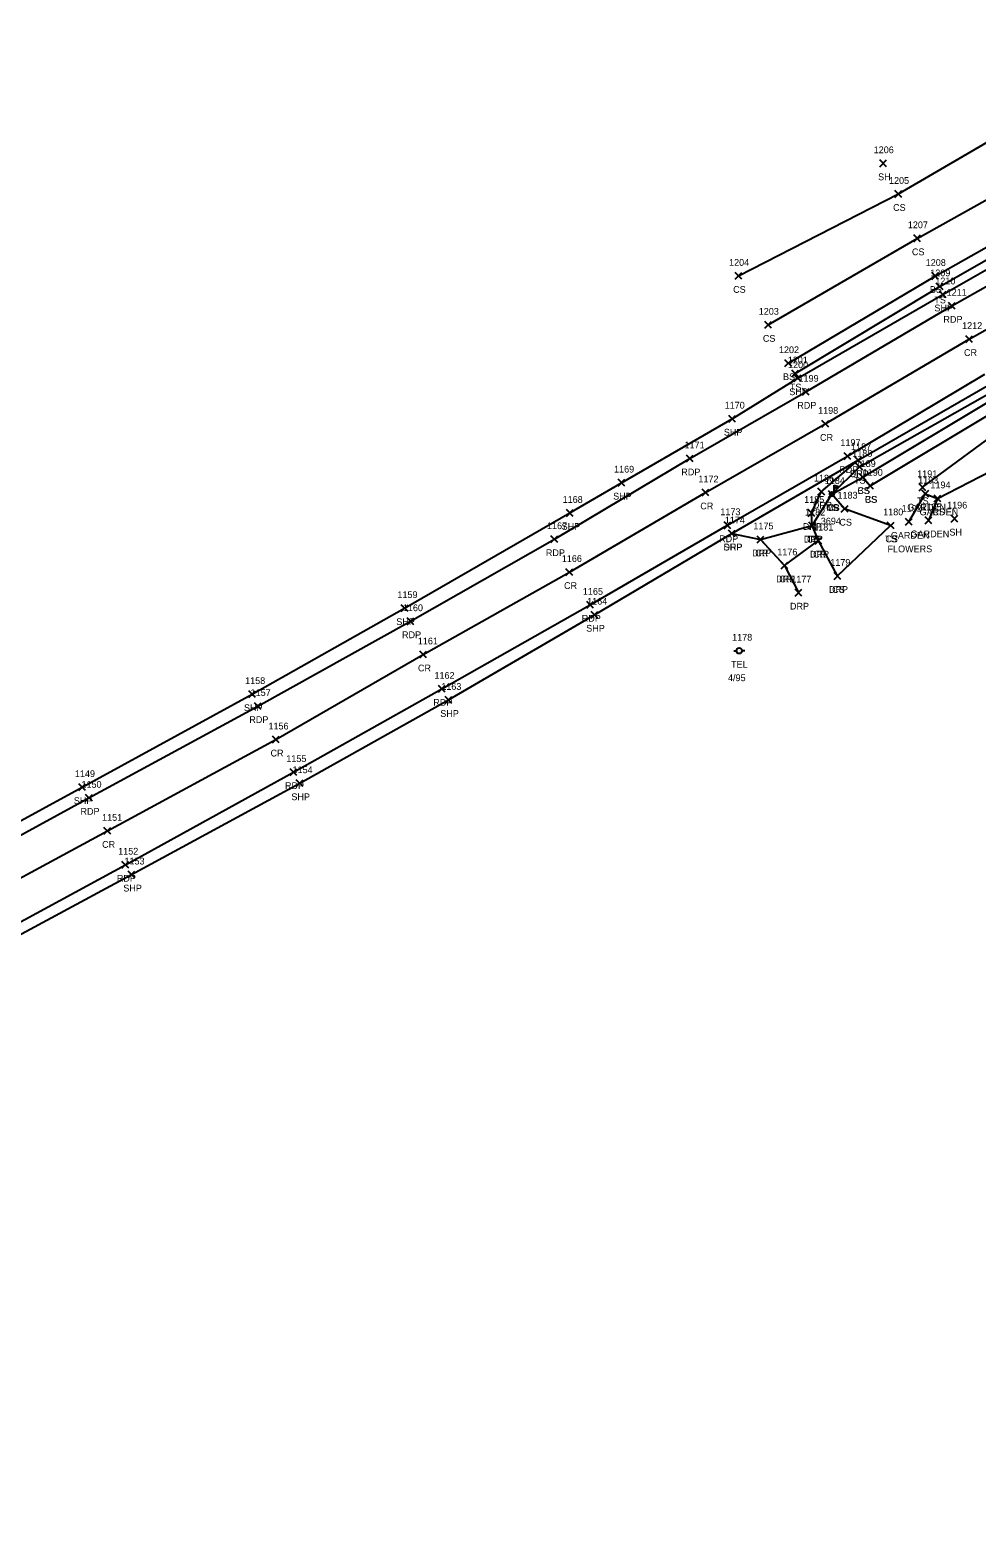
# Model space of a CAD drawing. Extents: x 1606530 to 1613020, y 784959 to 789666.
# Drawn here: x 1608585 to 1608865.5, y 787945.8 to 788392.4 of the extents above; entities that cross this region are included whole.
import ezdxf

# ---------------------------------------------------------------- set-up
doc = ezdxf.new("R2010")
doc.units = 0
for name, color, linetype in [('L_A', 7, 'Continuous'), ('L_C', 7, 'Continuous'), ('L_I', 7, 'Continuous'), ('L_TIC', 7, 'Continuous'), ('LAPB', 7, 'Continuous'), ('LELB', 7, 'Continuous'), ('LMB', 7, 'Continuous'), ('P_A', 7, 'Continuous'), ('P_I', 7, 'Continuous'), ('P_TIC', 7, 'Continuous'), ('PET', 7, 'Continuous'), ('PRC', 7, 'Continuous'), ('PSP', 7, 'Continuous'), ('R_A', 7, 'Continuous'), ('R_I', 7, 'Continuous'), ('R_TIC', 7, 'Continuous'), ('RDP', 7, 'Continuous'), ('U_A', 7, 'Continuous'), ('U_C', 7, 'Continuous'), ('U_I', 7, 'Continuous'), ('UP', 7, 'Continuous')]:
    doc.layers.add(name, color=color, linetype=linetype)

msp = doc.modelspace()

# ---------------------------------------------------------------- linework, layer by layer
at = {"layer": 'L_TIC'}
for points in [[(1608836.75, 788351.95), (1608838.75, 788353.95)], [(1608838.75, 788351.95), (1608836.75, 788353.95)], [(1608841.24, 788342.87), (1608843.24, 788344.87)], [(1608843.24, 788342.87), (1608841.24, 788344.87)], [(1608846.82, 788329.73), (1608848.82, 788331.73)], [(1608848.82, 788329.73), (1608846.82, 788331.73)], [(1608793.85, 788318.6), (1608795.85, 788320.6)], [(1608795.85, 788318.6), (1608793.85, 788320.6)], [(1608852.13, 788318.57), (1608854.13, 788320.57)], [(1608854.13, 788318.57), (1608852.13, 788320.57)], [(1608853.48, 788315.49), (1608855.48, 788317.49)], [(1608855.48, 788315.49), (1608853.48, 788317.49)], [(1608802.65, 788304.1), (1608804.65, 788306.1)], [(1608804.65, 788304.1), (1608802.65, 788306.1)], [(1608808.64, 788292.73), (1608810.64, 788294.73)], [(1608810.64, 788292.73), (1608808.64, 788294.73)], [(1608810.68, 788289.67), (1608812.68, 788291.67)], [(1608812.68, 788289.67), (1608810.68, 788291.67)], [(1608829.7, 788262.06), (1608831.7, 788264.06)], [(1608831.7, 788262.06), (1608829.7, 788264.06)], [(1608830.71, 788259.02), (1608832.71, 788261.02)], [(1608832.71, 788259.02), (1608830.71, 788261.02)], [(1608830.71, 788259.02), (1608832.71, 788261.02)], [(1608832.71, 788259.02), (1608830.71, 788261.02)], [(1608821.56, 788253.99), (1608823.56, 788255.99)], [(1608823.56, 788253.99), (1608821.56, 788255.99)], [(1608821.56, 788253.99), (1608823.56, 788255.99)], [(1608823.56, 788253.99), (1608821.56, 788255.99)], [(1608832.88, 788256.4), (1608834.88, 788258.4)], [(1608834.88, 788256.4), (1608832.88, 788258.4)], [(1608832.88, 788256.4), (1608834.88, 788258.4)], [(1608834.88, 788256.4), (1608832.88, 788258.4)], [(1608848.38, 788255.99), (1608850.38, 788257.99)], [(1608850.38, 788255.99), (1608848.38, 788257.99)], [(1608849.23, 788254.11), (1608851.23, 788256.11)], [(1608851.23, 788254.11), (1608849.23, 788256.11)], [(1608825.32, 788249.65), (1608827.32, 788251.65)], [(1608827.32, 788249.65), (1608825.32, 788251.65)], [(1608852.86, 788252.71), (1608854.86, 788254.71)], [(1608854.86, 788252.71), (1608852.86, 788254.71)], [(1608852.86, 788252.71), (1608854.86, 788254.71)], [(1608854.86, 788252.71), (1608852.86, 788254.71)], [(1608844.34, 788245.75), (1608846.34, 788247.75)], [(1608846.34, 788245.75), (1608844.34, 788247.75)], [(1608850.2, 788246.2), (1608852.2, 788248.2)], [(1608852.2, 788246.2), (1608850.2, 788248.2)], [(1608857.87, 788246.71), (1608859.87, 788248.71)], [(1608859.87, 788246.71), (1608857.87, 788248.71)], [(1608815.75, 788244.64), (1608817.75, 788246.64)], [(1608817.75, 788244.64), (1608815.75, 788246.64)], [(1608838.95, 788244.71), (1608840.95, 788246.71)], [(1608840.95, 788244.71), (1608838.95, 788246.71)], [(1608838.95, 788244.71), (1608840.95, 788246.71)], [(1608840.95, 788244.71), (1608838.95, 788246.71)], [(1608823.19, 788229.73), (1608825.19, 788231.73)], [(1608825.19, 788229.73), (1608823.19, 788231.73)]]:
    msp.add_lwpolyline(points, dxfattribs=at)
at = {"layer": 'LAPB'}
msp.add_lwpolyline([(1608845.34, 788246.75), (1608850.23, 788255.11), (1608853.86, 788253.71), (1608851.2, 788247.2)], dxfattribs=at)
at = {"layer": 'LELB'}
for points in [[(1608831.71, 788260.02), (1608870.92, 788283.54), (1608902.9, 788300.53), (1608905.17, 788302.06), (1608913.86, 788309.86), (1608916.94, 788311.14), (1608945.63, 788325.49), (1608982.98, 788345.36), (1609026.68, 788366.49), (1609062.42, 788381.05), (1609095.63, 788388.11), (1609108.11, 788392.39), (1609116.71, 788392.11), (1609124.65, 788392.27)], [(1608794.85, 788319.6), (1608842.24, 788343.87), (1608885.36, 788369.04), (1608910.12, 788379.88), (1608924.91, 788387.04)], [(1608803.65, 788305.1), (1608847.82, 788330.73), (1608888.11, 788353.15), (1608914.92, 788368.87), (1608930.01, 788374.18)], [(1608853.86, 788253.71), (1608879.11, 788266.69), (1608889.07, 788272.67), (1608908.34, 788283.28), (1608917.54, 788288.2), (1608929.97, 788294.46), (1608949.67, 788303.5), (1608962.88, 788306.16), (1608991.96, 788321.51), (1609035.12, 788349.67), (1609066.9, 788360.54), (1609090.16, 788369.42)], [(1608809.64, 788293.73), (1608853.13, 788319.57), (1608892.85, 788341.93), (1608925.8, 788363.52)], [(1608811.68, 788290.67), (1608854.48, 788316.49), (1608894.21, 788339.18), (1608933.71, 788362.09)], [(1608833.88, 788257.4), (1608872.6, 788280.62), (1608904.01, 788298), (1608902.9, 788300.53)], [(1608849.38, 788256.99), (1608875.12, 788276), (1608906.35, 788297.69), (1608905.17, 788302.06), (1608903.61, 788303.66)], [(1608816.75, 788245.64), (1608822.56, 788254.99), (1608830.7, 788263.06), (1608870.16, 788285.39)], [(1608824.19, 788230.73), (1608839.95, 788245.71), (1608826.32, 788250.65), (1608822.56, 788254.99), (1608831.71, 788260.02), (1608833.88, 788257.4)]]:
    msp.add_lwpolyline(points, dxfattribs=at)
at = {"layer": 'LMB'}
for p, q in [((1608823.21, 788257.59), (1608824.51, 788257.21)), ((1608823.22, 788255), (1608823.22, 788257.6)), ((1608823.22, 788256.69), (1608824.5, 788257.2)), ((1608822.56, 788254.99), (1608822.56, 788254.99))]:
    msp.add_line(p, q, dxfattribs=at)
msp.add_circle((1608822.56, 788254.99), 0.656, dxfattribs=at)
at = {"layer": 'P_TIC'}
for points in [[(1608854.39, 788313.11), (1608856.39, 788315.11)], [(1608856.39, 788313.11), (1608854.39, 788315.11)], [(1608857.1, 788309.73), (1608859.1, 788311.73)], [(1608859.1, 788309.73), (1608857.1, 788311.73)], [(1608862.25, 788299.9), (1608864.25, 788301.9)], [(1608864.25, 788299.9), (1608862.25, 788301.9)], [(1608811.41, 788288.29), (1608813.41, 788290.29)], [(1608813.41, 788288.29), (1608811.41, 788290.29)], [(1608813.8, 788284.27), (1608815.8, 788286.27)], [(1608815.8, 788284.27), (1608813.8, 788286.27)], [(1608791.98, 788276.31), (1608793.98, 788278.31)], [(1608793.98, 788276.31), (1608791.98, 788278.31)], [(1608819.6, 788274.76), (1608821.6, 788276.76)], [(1608821.6, 788274.76), (1608819.6, 788276.76)], [(1608779.44, 788264.54), (1608781.44, 788266.54)], [(1608781.44, 788264.54), (1608779.44, 788266.54)], [(1608826.2, 788265.24), (1608828.2, 788267.24)], [(1608828.2, 788265.24), (1608826.2, 788267.24)], [(1608829.36, 788264), (1608831.36, 788266)], [(1608831.36, 788264), (1608829.36, 788266)], [(1608759.2, 788257.36), (1608761.2, 788259.36)], [(1608761.2, 788257.36), (1608759.2, 788259.36)], [(1608784.13, 788254.45), (1608786.13, 788256.45)], [(1608786.13, 788254.45), (1608784.13, 788256.45)], [(1608743.94, 788248.39), (1608745.94, 788250.39)], [(1608745.94, 788248.39), (1608743.94, 788250.39)], [(1608739.32, 788240.6), (1608741.32, 788242.6)], [(1608741.32, 788240.6), (1608739.32, 788242.6)], [(1608790.64, 788244.74), (1608792.64, 788246.74)], [(1608792.64, 788244.74), (1608790.64, 788246.74)], [(1608791.93, 788242.28), (1608793.93, 788244.28)], [(1608793.93, 788242.28), (1608791.93, 788244.28)], [(1608800.42, 788240.54), (1608802.42, 788242.54)], [(1608802.42, 788240.54), (1608800.42, 788242.54)], [(1608815.75, 788244.64), (1608817.75, 788246.64)], [(1608817.75, 788244.64), (1608815.75, 788246.64)], [(1608817.57, 788240.19), (1608819.57, 788242.19)], [(1608819.57, 788240.19), (1608817.57, 788242.19)], [(1608807.54, 788232.85), (1608809.54, 788234.85)], [(1608809.54, 788232.85), (1608807.54, 788234.85)], [(1608743.76, 788230.88), (1608745.76, 788232.88)], [(1608745.76, 788230.88), (1608743.76, 788232.88)], [(1608694.96, 788220.19), (1608696.96, 788222.19)], [(1608696.96, 788220.19), (1608694.96, 788222.19)], [(1608749.94, 788221.17), (1608751.94, 788223.17)], [(1608751.94, 788221.17), (1608749.94, 788223.17)], [(1608751.22, 788218.24), (1608753.22, 788220.24)], [(1608753.22, 788218.24), (1608751.22, 788220.24)], [(1608696.7, 788216.31), (1608698.7, 788218.31)], [(1608698.7, 788216.31), (1608696.7, 788218.31)], [(1608700.47, 788206.47), (1608702.47, 788208.47)], [(1608702.47, 788206.47), (1608700.47, 788208.47)], [(1608705.97, 788196.28), (1608707.97, 788198.28)], [(1608707.97, 788196.28), (1608705.97, 788198.28)], [(1608649.82, 788194.72), (1608651.82, 788196.72)], [(1608651.82, 788194.72), (1608649.82, 788196.72)], [(1608651.45, 788191.19), (1608653.45, 788193.19)], [(1608653.45, 788191.19), (1608651.45, 788193.19)], [(1608707.99, 788193), (1608709.99, 788195)], [(1608709.99, 788193), (1608707.99, 788195)], [(1608656.8, 788181.27), (1608658.8, 788183.27)], [(1608658.8, 788181.27), (1608656.8, 788183.27)], [(1608662.01, 788171.64), (1608664.01, 788173.64)], [(1608664.01, 788171.64), (1608662.01, 788173.64)], [(1608599.4, 788167.18), (1608601.4, 788169.18)], [(1608601.4, 788167.18), (1608599.4, 788169.18)], [(1608663.87, 788168.33), (1608665.87, 788170.33)], [(1608665.87, 788168.33), (1608663.87, 788170.33)], [(1608601.43, 788164), (1608603.43, 788166)], [(1608603.43, 788164), (1608601.43, 788166)], [(1608606.88, 788154.22), (1608608.88, 788156.22)], [(1608608.88, 788154.22), (1608606.88, 788156.22)], [(1608612.21, 788144.21), (1608614.21, 788146.21)], [(1608614.21, 788144.21), (1608612.21, 788146.21)], [(1608614.07, 788141.28), (1608616.07, 788143.28)], [(1608616.07, 788141.28), (1608614.07, 788143.28)]]:
    msp.add_lwpolyline(points, dxfattribs=at)
at = {"layer": 'PET'}
for points in [[(1608213.49, 787970.47), (1608262.25, 787993.4), (1608276.88, 787999.74), (1608323.57, 788022.14), (1608370.66, 788045.01), (1608417.98, 788068.46), (1608464.64, 788091.66), (1608509.37, 788115.25), (1608554.28, 788138.75), (1608602.43, 788165), (1608652.45, 788192.19), (1608697.7, 788217.31), (1608740.32, 788241.6), (1608780.44, 788265.54), (1608814.8, 788285.27), (1608858.1, 788310.73), (1608896.56, 788332.46)], [(1608222.94, 787950.09), (1608271.33, 787972.62), (1608285.55, 787979.14), (1608332.21, 788001.49), (1608379.48, 788024.01), (1608428.02, 788048.6), (1608475.06, 788071.87), (1608519, 788095), (1608563.86, 788118.44), (1608613.21, 788145.21), (1608663.01, 788172.64), (1608706.97, 788197.28), (1608750.94, 788222.17), (1608791.64, 788245.74), (1608827.2, 788266.24), (1608867.86, 788290.54)]]:
    msp.add_lwpolyline(points, dxfattribs=at)
at = {"layer": 'PRC'}
for points in [[(1608218.84, 787960.71), (1608267.22, 787983.04), (1608281.29, 787989.52), (1608328.06, 788011.76), (1608375.14, 788034.19), (1608423.06, 788058.55), (1608469.95, 788081.45), (1608514.06, 788104.91), (1608558.92, 788128.79), (1608607.88, 788155.22), (1608657.8, 788182.27), (1608701.47, 788207.47), (1608744.76, 788231.88), (1608785.13, 788255.45), (1608820.6, 788275.76), (1608863.25, 788300.9), (1608901.81, 788322.6)], [(1608801.42, 788241.54), (1608816.75, 788245.64)], [(1608808.54, 788233.85), (1608818.57, 788241.19)]]:
    msp.add_lwpolyline(points, dxfattribs=at)
at = {"layer": 'PSP'}
for points in [[(1608211.38, 787974.27), (1608260.55, 787996.78), (1608275.47, 788003.59), (1608321.31, 788025.42), (1608369.02, 788048.35), (1608416.07, 788071.69), (1608462.93, 788095.28), (1608507.55, 788118.54), (1608552.21, 788141.92), (1608600.4, 788168.18), (1608650.82, 788195.72), (1608695.96, 788221.19), (1608744.94, 788249.39), (1608760.2, 788258.36), (1608792.98, 788277.31), (1608812.41, 788289.29), (1608855.39, 788314.11), (1608894.81, 788336.59)], [(1608222.38, 787945.84), (1608249.08, 787958.77), (1608292.52, 787977.73), (1608320.86, 787991.5), (1608334.01, 787997.98), (1608381.01, 788020.88), (1608430, 788045.59), (1608476.4, 788068.65), (1608521.08, 788091.65), (1608567.38, 788116.6), (1608615.07, 788142.28), (1608664.87, 788169.33), (1608708.99, 788194), (1608752.22, 788219.24), (1608792.93, 788243.28), (1608830.36, 788265), (1608869.22, 788287.4)]]:
    msp.add_lwpolyline(points, dxfattribs=at)
at = {"layer": 'R_TIC'}
for points in [[(1608829.36, 788264), (1608831.36, 788266)], [(1608831.36, 788264), (1608829.36, 788266)], [(1608818.41, 788254.7), (1608820.41, 788256.7)], [(1608820.41, 788254.7), (1608818.41, 788256.7)], [(1608815.47, 788248.38), (1608817.47, 788250.38)], [(1608817.47, 788248.38), (1608815.47, 788250.38)], [(1608791.93, 788242.28), (1608793.93, 788244.28)], [(1608793.93, 788242.28), (1608791.93, 788244.28)], [(1608800.42, 788240.54), (1608802.42, 788242.54)], [(1608802.42, 788240.54), (1608800.42, 788242.54)], [(1608815.75, 788244.64), (1608817.75, 788246.64)], [(1608817.75, 788244.64), (1608815.75, 788246.64)], [(1608817.57, 788240.19), (1608819.57, 788242.19)], [(1608819.57, 788240.19), (1608817.57, 788242.19)], [(1608807.54, 788232.85), (1608809.54, 788234.85)], [(1608809.54, 788232.85), (1608807.54, 788234.85)], [(1608823.19, 788229.73), (1608825.19, 788231.73)], [(1608825.19, 788229.73), (1608823.19, 788231.73)], [(1608811.63, 788224.79), (1608813.63, 788226.79)], [(1608813.63, 788224.79), (1608811.63, 788226.79)]]:
    msp.add_lwpolyline(points, dxfattribs=at)
at = {"layer": 'RDP'}
for points in [[(1608824.19, 788230.73), (1608818.57, 788241.19), (1608816.75, 788245.64), (1608816.47, 788249.38), (1608819.41, 788255.7), (1608830.36, 788265)], [(1608792.93, 788243.28), (1608801.42, 788241.54), (1608808.54, 788233.85), (1608812.63, 788225.79)]]:
    msp.add_lwpolyline(points, dxfattribs=at)
at = {"layer": 'UP'}
for p, q in [((1608793.45, 788208.57), (1608794.28, 788208.57)), ((1608795.11, 788208.58), (1608795.11, 788208.58)), ((1608796.78, 788208.58), (1608795.95, 788208.58)), ((1608795.95, 788208.58), (1608795.95, 788208.58)), ((1608796.78, 788208.58), (1608796.78, 788208.58))]:
    msp.add_line(p, q, dxfattribs=at)
msp.add_circle((1608795.11, 788208.58), 0.833, dxfattribs=at)

# ---------------------------------------------------------------- texts
at = {"layer": 'L_A'}
for s, p in [('SH', (1608836.24, 788347.95)), ('CS', (1608840.68, 788338.87)), ('CS', (1608846.26, 788325.73)), ('CS', (1608793.29, 788314.6)), ('BS', (1608851.57, 788314.57)), ('TS', (1608852.89, 788311.49)), ('CS', (1608802.09, 788300.1)), ('BS', (1608808.08, 788288.73)), ('TS', (1608810.09, 788285.67)), ('TS', (1608829.11, 788258.06)), ('CS', (1608830.15, 788255.02)), ('BS', (1608830.15, 788255.02)), ('TS', (1608820.97, 788249.99)), ('MB', (1608820.87, 788249.99)), ('CS', (1608821, 788249.99)), ('CS', (1608832.32, 788252.4)), ('BS', (1608832.32, 788252.4)), ('GARDEN', (1608844.9, 788250.11)), ('TS', (1608847.79, 788251.99)), ('CS', (1608824.77, 788245.65)), ('GARDEN', (1608848.53, 788248.71)), ('CS', (1608852.3, 788248.71)), ('TS', (1608815.16, 788240.64)), ('TS', (1608838.36, 788240.71)), ('CS', (1608838.39, 788240.71)), ('GARDEN', (1608840.01, 788241.75)), ('GARDEN', (1608845.87, 788242.2)), ('SH', (1608857.36, 788242.71)), ('CS', (1608822.63, 788225.73))]:
    msp.add_text(s, height=2, dxfattribs=at).set_placement(p)
at = {"layer": 'L_C'}
for s, p in [('3694', (1608819.26, 788245.99)), ('FLOWERS', (1608839.04, 788237.75))]:
    msp.add_text(s, height=2, dxfattribs=at).set_placement(p)
at = {"layer": 'L_I'}
for s, p in [('1206', (1608834.93, 788355.95)), ('1205', (1608839.47, 788346.87)), ('1207', (1608845.05, 788333.73)), ('1204', (1608792.08, 788322.6)), ('1208', (1608850.35, 788322.57)), ('1209', (1608851.7, 788319.49)), ('1203', (1608800.88, 788308.1)), ('1202', (1608806.86, 788296.73)), ('1201', (1608809.48, 788293.67)), ('1188', (1608828.57, 788266.06)), ('1189', (1608829.58, 788263.02)), ('1189', (1608829.58, 788263.02)), ('1190', (1608831.67, 788260.4)), ('1190', (1608831.67, 788260.4)), ('1191', (1608847.82, 788259.99)), ('1184', (1608820.44, 788257.99)), ('1184', (1608820.44, 788257.99)), ('1184', (1608820.44, 788257.99)), ('1193', (1608848.1, 788258.11)), ('1194', (1608851.74, 788256.71)), ('1194', (1608851.74, 788256.71)), ('1183', (1608824.2, 788253.65)), ('1192', (1608843.22, 788249.75)), ('1195', (1608849.07, 788250.2)), ('1196', (1608856.69, 788250.71)), ('1182', (1608814.62, 788248.64)), ('1180', (1608837.74, 788248.71)), ('1180', (1608837.74, 788248.71)), ('1179', (1608822.06, 788233.73))]:
    msp.add_text(s, height=2, dxfattribs=at).set_placement(p)
at = {"layer": 'P_A'}
for s, p in [('SHP', (1608852.92, 788309.11)), ('RDP', (1608855.59, 788305.73)), ('CR', (1608861.69, 788295.9)), ('SHP', (1608809.94, 788284.29)), ('RDP', (1608812.29, 788280.27)), ('SHP', (1608790.52, 788272.31)), ('CR', (1608819.03, 788270.76)), ('RDP', (1608777.93, 788260.54)), ('RDP', (1608824.69, 788261.24)), ('SHP', (1608827.89, 788260)), ('SHP', (1608757.73, 788253.36)), ('CR', (1608783.56, 788250.45)), ('SHP', (1608742.47, 788244.39)), ('RDP', (1608789.13, 788240.74)), ('CR', (1608815.18, 788240.64)), ('RDP', (1608737.81, 788236.6)), ('SHP', (1608790.47, 788238.28)), ('CR', (1608799.85, 788236.54)), ('CR', (1608817, 788236.19)), ('CR', (1608806.97, 788228.85)), ('CR', (1608743.19, 788226.88)), ('SHP', (1608693.49, 788216.19)), ('RDP', (1608748.43, 788217.17)), ('SHP', (1608749.76, 788214.24)), ('RDP', (1608695.19, 788212.31)), ('CR', (1608699.91, 788202.47)), ('RDP', (1608704.46, 788192.28)), ('SHP', (1608648.36, 788190.72)), ('RDP', (1608649.94, 788187.19)), ('SHP', (1608706.52, 788189)), ('CR', (1608656.23, 788177.27)), ('RDP', (1608660.5, 788167.64)), ('SHP', (1608597.94, 788163.18)), ('RDP', (1608599.92, 788160)), ('SHP', (1608662.41, 788164.33)), ('CR', (1608606.32, 788150.22)), ('RDP', (1608610.7, 788140.21)), ('SHP', (1608612.61, 788137.28))]:
    msp.add_text(s, height=2, dxfattribs=at).set_placement(p)
at = {"layer": 'P_I'}
for s, p in [('1210', (1608853.18, 788317.11)), ('1211', (1608856.54, 788313.73)), ('1212', (1608861.13, 788303.9)), ('1200', (1608809.55, 788292.29)), ('1199', (1608812.66, 788288.27)), ('1170', (1608790.77, 788280.31)), ('1198', (1608818.47, 788278.76)), ('1171', (1608778.88, 788268.54)), ('1197', (1608825.07, 788269.24)), ('1187', (1608828.23, 788268)), ('1169', (1608758.01, 788261.36)), ('1172', (1608783, 788258.45)), ('1168', (1608742.77, 788252.39)), ('1173', (1608789.51, 788248.74)), ('1174', (1608790.81, 788246.28)), ('1182', (1608814.62, 788248.64)), ('1167', (1608738.14, 788244.6)), ('1175', (1608799.29, 788244.54)), ('1181', (1608817.01, 788244.19)), ('1176', (1608806.36, 788236.85)), ('1166', (1608742.53, 788234.88)), ('1159', (1608693.82, 788224.19)), ('1165', (1608748.77, 788225.17)), ('1160', (1608695.44, 788220.31)), ('1164', (1608750.05, 788222.24)), ('1161', (1608699.87, 788210.47)), ('1162', (1608704.8, 788200.28)), ('1158', (1608648.7, 788198.72)), ('1163', (1608706.81, 788197)), ('1157', (1608650.33, 788195.19)), ('1156', (1608655.62, 788185.27)), ('1155', (1608660.89, 788175.64)), ('1149', (1608598.27, 788171.18)), ('1154', (1608662.75, 788172.33)), ('1150', (1608600.22, 788168)), ('1151', (1608606.32, 788158.22)), ('1152', (1608611.09, 788148.21)), ('1153', (1608612.95, 788145.28))]:
    msp.add_text(s, height=2, dxfattribs=at).set_placement(p)
at = {"layer": 'R_A'}
for p in [(1608827.84, 788260), (1608816.9, 788250.7), (1608813.95, 788244.38), (1608814.23, 788240.64), (1608790.42, 788238.28), (1608798.91, 788236.54), (1608816.06, 788236.19), (1608806.03, 788228.85), (1608821.68, 788225.73), (1608810.12, 788220.79)]:
    msp.add_text('DRP', height=2, dxfattribs=at).set_placement(p)
at = {"layer": 'R_I'}
for s, p in [('1187', (1608828.23, 788268)), ('1186', (1608817.23, 788258.7)), ('1185', (1608814.34, 788252.38)), ('1174', (1608790.81, 788246.28)), ('1182', (1608814.62, 788248.64)), ('1175', (1608799.29, 788244.54)), ('1181', (1608817.01, 788244.19)), ('1176', (1608806.36, 788236.85)), ('1179', (1608822.06, 788233.73)), ('1177', (1608810.51, 788228.79))]:
    msp.add_text(s, height=2, dxfattribs=at).set_placement(p)
at = {"layer": 'U_A'}
msp.add_text('TEL', height=2, dxfattribs=at).set_placement((1608792.67, 788203.58))
at = {"layer": 'U_C'}
msp.add_text('4/95', height=2, dxfattribs=at).set_placement((1608791.77, 788199.58))
at = {"layer": 'U_I'}
msp.add_text('1178', height=2, dxfattribs=at).set_placement((1608792.99, 788211.58))

doc.saveas('drawing.dxf')
